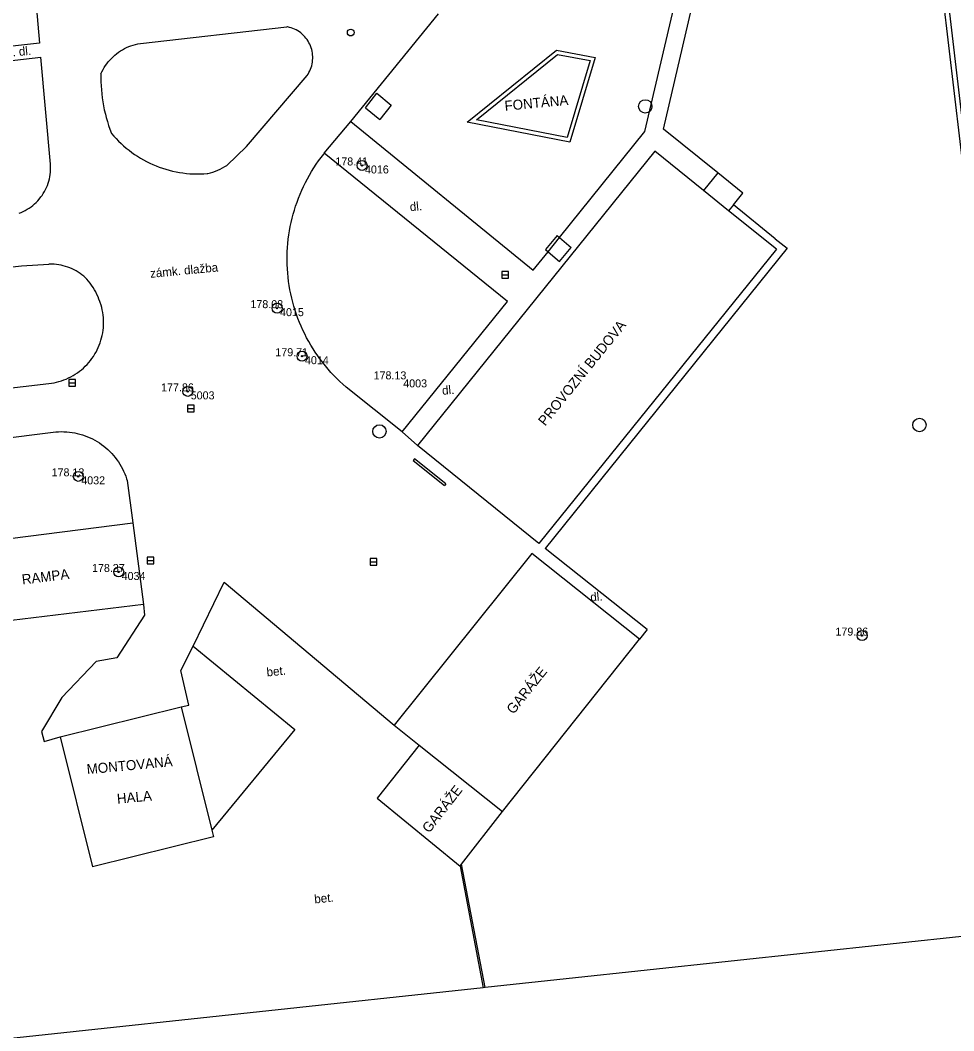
# Model space of a CAD drawing. Extents: x -539515 to -538098, y -1182060 to -1180157.
# Drawn here: x -539294 to -539224, y -1181270.6 to -1181194.9 of the extents above; entities that cross this region are included whole.
import ezdxf

# ---------------------------------------------------------------- set-up
doc = ezdxf.new("R2010")
doc.units = 0
for name, color, linetype in [('Vrstva 1', 7, 'Continuous'), ('Vrstva 13', 7, 'Continuous'), ('Vrstva 21', 7, 'Continuous'), ('Vrstva 22', 7, 'Continuous'), ('Vrstva 23', 7, 'Continuous'), ('Vrstva 27', 7, 'Continuous'), ('Vrstva 28', 7, 'Continuous'), ('Vrstva 40', 7, 'Continuous'), ('Vrstva 41', 7, 'Continuous'), ('Vrstva 68', 7, 'Continuous'), ('Vrstva 88', 7, 'Continuous')]:
    doc.layers.add(name, color=color, linetype=linetype)

msp = doc.modelspace()

# ---------------------------------------------------------------- linework, layer by layer
at = {"layer": 'Vrstva 1'}
for p, q in [((-539246.42, -1181204.7), (-539264.22, -1181226.76)), ((-539237.29, -1181212.03), (-539255.115, -1181234.107)), ((-539255.115, -1181234.107), (-539264.22, -1181226.76)), ((-539285.57, -1181232.55), (-539284.79, -1181238.68)), ((-539255.644, -1181234.863), (-539265.99, -1181247.73)), ((-539247.571, -1181241.284), (-539255.644, -1181234.863)), ((-539257.852, -1181254.21), (-539247.571, -1181241.284)), ((-539291.02, -1181248.59), (-539281.95, -1181246.35)), ((-539291.02, -1181248.59), (-539288.61, -1181258.34)), ((-539279.54, -1181256.1), (-539288.61, -1181258.34))]:
    msp.add_line(p, q, dxfattribs=at)
for points in [[(-539242.774, -1181207.642), (-539246.42, -1181204.7)], [(-539240.891, -1181209.161), (-539242.774, -1181207.642)], [(-539237.29, -1181212.03), (-539240.891, -1181209.161)], [(-539284.79, -1181238.68), (-539297.997, -1181240.285), (-539298.761, -1181234.225), (-539285.57, -1181232.55)], [(-539281.95, -1181246.35), (-539279.661, -1181255.611), (-539279.54, -1181256.1)], [(-539265.99, -1181247.73), (-539264.107, -1181249.236), (-539257.852, -1181254.21)], [(-539264.107, -1181249.236), (-539267.251, -1181253.192), (-539261.04, -1181258.3), (-539260.918, -1181258.143), (-539257.852, -1181254.21)]]:
    msp.add_lwpolyline(points, dxfattribs=at)
at = {"layer": 'Vrstva 13'}
for p, q in [((-539247.18, -1181203.22), (-539243.07, -1181185.65)), ((-539245.78, -1181203.04), (-539241.83, -1181186.08)), ((-539292.58, -1181196.58), (-539296.413, -1181197.009)), ((-539260.498, -1181202.509), (-539253.799, -1181197.109)), ((-539253.799, -1181197.109), (-539250.902, -1181197.657)), ((-539296.519, -1181198.119), (-539292.47, -1181197.64)), ((-539259.81, -1181202.339), (-539253.719, -1181197.429)), ((-539253.719, -1181197.429), (-539251.283, -1181197.889)), ((-539251.283, -1181197.889), (-539253, -1181203.674)), ((-539250.902, -1181197.657), (-539252.791, -1181204.02)), ((-539268.14, -1181201.43), (-539267.28, -1181200.35)), ((-539267.28, -1181200.35), (-539266.2, -1181201.24)), ((-539268.14, -1181201.43), (-539267.06, -1181202.32)), ((-539266.2, -1181201.24), (-539267.06, -1181202.32)), ((-539269.22, -1181202.46), (-539255.54, -1181213.6)), ((-539253, -1181203.674), (-539259.81, -1181202.339)), ((-539252.791, -1181204.02), (-539260.498, -1181202.509)), ((-539253.58, -1181211.166), (-539247.18, -1181203.22)), ((-539257.48, -1181215.97), (-539271.22, -1181204.85)), ((-539241.711, -1181206.324), (-539242.774, -1181207.642)), ((-539240.53, -1181208.72), (-539239.82, -1181207.85)), ((-539240.53, -1181208.72), (-539240.891, -1181209.161)), ((-539237.39, -1181211.25), (-539240.53, -1181208.72)), ((-539237.39, -1181211.25), (-539236.503, -1181211.965)), ((-539236.503, -1181211.965), (-539254.661, -1181234.469)), ((-539254.435, -1181212.227), (-539253.58, -1181212.96)), ((-539253.58, -1181212.96), (-539252.7, -1181211.92)), ((-539265.37, -1181225.74), (-539257.48, -1181215.97)), ((-539264.46, -1181227.765), (-539264.56, -1181227.89)), ((-539264.56, -1181227.89), (-539262.199, -1181229.767)), ((-539262.099, -1181229.642), (-539264.46, -1181227.765)), ((-539262.099, -1181229.642), (-539262.199, -1181229.767)), ((-539246.998, -1181240.564), (-539254.661, -1181234.469)), ((-539246.998, -1181240.564), (-539247.571, -1181241.284)), ((-539281.06, -1181241.8), (-539273.42, -1181248.06)), ((-539273.42, -1181248.06), (-539279.661, -1181255.611))]:
    msp.add_line(p, q, dxfattribs=at)
for points in [[(-539241.711, -1181206.324), (-539245.78, -1181203.04)], [(-539239.82, -1181207.85), (-539241.711, -1181206.324)], [(-539255.54, -1181213.6), (-539254.435, -1181212.227), (-539253.58, -1181211.166)], [(-539253.75, -1181211.02), (-539254.63, -1181212.06), (-539254.435, -1181212.227)], [(-539253.75, -1181211.02), (-539253.58, -1181211.166), (-539252.7, -1181211.92)]]:
    msp.add_lwpolyline(points, dxfattribs=at)
at = {"layer": 'Vrstva 21'}
for centre, radius in [((-539268.39, -1181205.76), 0.375), ((-539268.39, -1181205.76), 0.05), ((-539274.76, -1181216.46), 0.375), ((-539274.76, -1181216.46), 0.05), ((-539272.89, -1181220.06), 0.375), ((-539272.89, -1181220.06), 0.05), ((-539281.46, -1181222.7), 0.375), ((-539281.46, -1181222.7), 0.05), ((-539289.67, -1181229.07), 0.375), ((-539289.67, -1181229.07), 0.05), ((-539286.64, -1181236.24), 0.375), ((-539286.64, -1181236.24), 0.05), ((-539230.88, -1181241.01), 0.375), ((-539230.88, -1181241.01), 0.05)]:
    msp.add_circle(centre, radius, dxfattribs=at)
at = {"layer": 'Vrstva 27'}
for p, q in [((-539257.9, -1181213.96), (-539257.4, -1181213.96)), ((-539290.39, -1181222.05), (-539289.89, -1181222.05)), ((-539281.47, -1181223.99), (-539280.97, -1181223.99)), ((-539284.5, -1181235.37), (-539284, -1181235.37)), ((-539267.78, -1181235.47), (-539267.28, -1181235.47))]:
    msp.add_line(p, q, dxfattribs=at)
for points in [[(-539257.9, -1181214.21), (-539257.4, -1181214.21), (-539257.4, -1181213.71), (-539257.9, -1181213.71)], [(-539290.39, -1181222.3), (-539289.89, -1181222.3), (-539289.89, -1181221.8), (-539290.39, -1181221.8)], [(-539281.47, -1181224.24), (-539280.97, -1181224.24), (-539280.97, -1181223.74), (-539281.47, -1181223.74)], [(-539284.5, -1181235.62), (-539284, -1181235.62), (-539284, -1181235.12), (-539284.5, -1181235.12)], [(-539267.78, -1181235.72), (-539267.28, -1181235.72), (-539267.28, -1181235.22), (-539267.78, -1181235.22)]]:
    msp.add_lwpolyline(points, close=True, dxfattribs=at)
for centre in [(-539247.14, -1181201.33), (-539267.08, -1181225.7), (-539226.58, -1181225.22)]:
    msp.add_circle(centre, 0.5, dxfattribs=at)
at = {"layer": 'Vrstva 28'}
msp.add_circle((-539269.24, -1181195.8), 0.25, dxfattribs=at)
at = {"layer": 'Vrstva 68'}
msp.add_line((-539226.807, -1181176.359), (-539216.629, -1181262.839), dxfattribs=at)
for points in [[(-539218.64, -1181242.5), (-539228.76, -1181156.37)], [(-539216.292, -1181262.8), (-539216.629, -1181262.839), (-539259.16, -1181267.405), (-539259.309, -1181267.421), (-539292.857, -1181271.023), (-539319.19, -1181273.85)]]:
    msp.add_lwpolyline(points, dxfattribs=at)
at = {"layer": 'Vrstva 88'}
for p, q in [((-539293.25, -1181189), (-539292.58, -1181196.58)), ((-539269.22, -1181202.46), (-539262.66, -1181194.38)), ((-539285, -1181196.61), (-539274.04, -1181195.36)), ((-539291.76, -1181205.66), (-539292.47, -1181197.64)), ((-539277.05, -1181204.33), (-539272.51, -1181199.02)), ((-539271.22, -1181204.85), (-539269.22, -1181202.46)), ((-539278.52, -1181205.76), (-539277.05, -1181204.33)), ((-539314.8, -1181215.68), (-539293.93, -1181213.28)), ((-539293.93, -1181213.28), (-539291.89, -1181213.17)), ((-539313.77, -1181224.67), (-539291.87, -1181222.11)), ((-539265.37, -1181225.74), (-539269.58, -1181222.38)), ((-539297.51, -1181226.52), (-539291.55, -1181225.76)), ((-539265.37, -1181225.74), (-539264.22, -1181226.76)), ((-539286.01, -1181229.38), (-539285.57, -1181232.55)), ((-539281.06, -1181241.8), (-539278.72, -1181237)), ((-539278.72, -1181237), (-539265.99, -1181247.73)), ((-539284.79, -1181238.68), (-539284.71, -1181239.48)), ((-539284.71, -1181239.48), (-539286.79, -1181242.67)), ((-539281.98, -1181243.63), (-539281.06, -1181241.8)), ((-539288.33, -1181242.95), (-539290.9, -1181245.65)), ((-539286.79, -1181242.67), (-539288.33, -1181242.95)), ((-539281.38, -1181246.22), (-539281.98, -1181243.63)), ((-539290.9, -1181245.65), (-539292.43, -1181248.2)), ((-539281.95, -1181246.35), (-539281.38, -1181246.22)), ((-539292.43, -1181248.2), (-539292.24, -1181248.94)), ((-539292.24, -1181248.94), (-539291.02, -1181248.59)), ((-539261.04, -1181258.3), (-539259.309, -1181267.421)), ((-539259.16, -1181267.405), (-539260.918, -1181258.143))]:
    msp.add_line(p, q, dxfattribs=at)
for points in [[(-539272.51, -1181199.02), (-539272.435, -1181198.906), (-539272.366, -1181198.787), (-539272.304, -1181198.665), (-539272.25, -1181198.54), (-539272.203, -1181198.411), (-539272.163, -1181198.28), (-539272.132, -1181198.147), (-539272.108, -1181198.012), (-539272.092, -1181197.876), (-539272.084, -1181197.739), (-539272.084, -1181197.602), (-539272.092, -1181197.466), (-539272.108, -1181197.33), (-539272.132, -1181197.195), (-539272.164, -1181197.062), (-539272.2, -1181196.94), (-539272.25, -1181196.802), (-539272.305, -1181196.676), (-539272.366, -1181196.554), (-539272.435, -1181196.436), (-539272.511, -1181196.322), (-539272.593, -1181196.212), (-539272.681, -1181196.107), (-539272.775, -1181196.008), (-539272.875, -1181195.915), (-539272.981, -1181195.827), (-539273.091, -1181195.746), (-539273.205, -1181195.671), (-539273.324, -1181195.603), (-539273.447, -1181195.542), (-539273.573, -1181195.489), (-539273.702, -1181195.443), (-539273.833, -1181195.404), (-539273.967, -1181195.373), (-539274.04, -1181195.36)], [(-539287.97, -1181198.89), (-539287.896, -1181198.73), (-539287.815, -1181198.574), (-539287.727, -1181198.422), (-539287.632, -1181198.274), (-539287.531, -1181198.13), (-539287.423, -1181197.992), (-539287.309, -1181197.858), (-539287.189, -1181197.729), (-539287.063, -1181197.607), (-539286.99, -1181197.54), (-539286.932, -1181197.49), (-539286.796, -1181197.379), (-539286.654, -1181197.274), (-539286.508, -1181197.176), (-539286.358, -1181197.085), (-539286.204, -1181197), (-539286.046, -1181196.923), (-539285.885, -1181196.853), (-539285.72, -1181196.79), (-539285.553, -1181196.735), (-539285.384, -1181196.688), (-539285.213, -1181196.648), (-539285, -1181196.61)], [(-539287.97, -1181198.89), (-539287.974, -1181199.192), (-539287.97, -1181199.493), (-539287.957, -1181199.795), (-539287.937, -1181200.096), (-539287.909, -1181200.397), (-539287.873, -1181200.696), (-539287.829, -1181200.995), (-539287.777, -1181201.292), (-539287.717, -1181201.588), (-539287.64, -1181201.92), (-539287.574, -1181202.174), (-539287.491, -1181202.464), (-539287.4, -1181202.752), (-539287.302, -1181203.037), (-539287.18, -1181203.36)], [(-539287.18, -1181203.36), (-539287.009, -1181203.557), (-539286.833, -1181203.749), (-539286.65, -1181203.936), (-539286.462, -1181204.116), (-539286.269, -1181204.291), (-539286.07, -1181204.46), (-539285.866, -1181204.623), (-539285.657, -1181204.779), (-539285.444, -1181204.929), (-539285.226, -1181205.072), (-539285.004, -1181205.209), (-539284.777, -1181205.339), (-539284.547, -1181205.461), (-539284.313, -1181205.577), (-539284.076, -1181205.685), (-539283.836, -1181205.786), (-539283.592, -1181205.88), (-539283.346, -1181205.966), (-539283.097, -1181206.044), (-539282.846, -1181206.115), (-539282.593, -1181206.178), (-539282.338, -1181206.233), (-539282.082, -1181206.281), (-539281.824, -1181206.32), (-539281.565, -1181206.352), (-539281.305, -1181206.376), (-539281.045, -1181206.391), (-539280.784, -1181206.399), (-539280.523, -1181206.399), (-539280.263, -1181206.391), (-539280.002, -1181206.374), (-539279.95, -1181206.37)], [(-539273.962, -1181213.824), (-539273.985, -1181213.507), (-539273.999, -1181213.189), (-539274.006, -1181212.871), (-539274.004, -1181212.553), (-539273.995, -1181212.235), (-539273.978, -1181211.918), (-539273.952, -1181211.601), (-539273.919, -1181211.284), (-539273.878, -1181210.969), (-539273.828, -1181210.655), (-539273.771, -1181210.342), (-539273.706, -1181210.03), (-539273.633, -1181209.721), (-539273.553, -1181209.413), (-539273.465, -1181209.107), (-539273.369, -1181208.804), (-539273.265, -1181208.503), (-539273.154, -1181208.205), (-539273.036, -1181207.91), (-539272.91, -1181207.618), (-539272.777, -1181207.329), (-539272.636, -1181207.044), (-539272.489, -1181206.762), (-539272.334, -1181206.484), (-539272.172, -1181206.21), (-539272.004, -1181205.94), (-539271.829, -1181205.675), (-539271.647, -1181205.414), (-539271.459, -1181205.157), (-539271.264, -1181204.906), (-539271.22, -1181204.85)], [(-539294.107, -1181209.337), (-539293.949, -1181209.275), (-539293.795, -1181209.205), (-539293.643, -1181209.129), (-539293.496, -1181209.045), (-539293.352, -1181208.954), (-539293.213, -1181208.856), (-539293.079, -1181208.753), (-539292.95, -1181208.642), (-539292.826, -1181208.526), (-539292.708, -1181208.405), (-539292.595, -1181208.277), (-539292.47, -1181208.12), (-539292.389, -1181208.008), (-539292.296, -1181207.866), (-539292.209, -1181207.72), (-539292.13, -1181207.57), (-539292.057, -1181207.417), (-539291.992, -1181207.26), (-539291.934, -1181207.1), (-539291.884, -1181206.938), (-539291.842, -1181206.774), (-539291.807, -1181206.607), (-539291.78, -1181206.44), (-539291.762, -1181206.271), (-539291.751, -1181206.102), (-539291.748, -1181205.932), (-539291.753, -1181205.762), (-539291.76, -1181205.66)], [(-539279.95, -1181206.37), (-539279.759, -1181206.318), (-539279.57, -1181206.259), (-539279.383, -1181206.192), (-539279.2, -1181206.117), (-539279.019, -1181206.035), (-539278.842, -1181205.946), (-539278.669, -1181205.85), (-539278.52, -1181205.76)], [(-539289.13, -1181214.18), (-539289.26, -1181214.064), (-539289.396, -1181213.955), (-539289.536, -1181213.852), (-539289.681, -1181213.755), (-539289.83, -1181213.665), (-539289.983, -1181213.582), (-539290.14, -1181213.507), (-539290.3, -1181213.438), (-539290.463, -1181213.377), (-539290.629, -1181213.324), (-539290.797, -1181213.278), (-539290.967, -1181213.24), (-539291.139, -1181213.209), (-539291.311, -1181213.187), (-539291.485, -1181213.173), (-539291.659, -1181213.166), (-539291.833, -1181213.168), (-539291.89, -1181213.17)], [(-539269.58, -1181222.38), (-539269.819, -1181222.17), (-539270.053, -1181221.954), (-539270.281, -1181221.733), (-539270.504, -1181221.506), (-539270.72, -1181221.273), (-539270.931, -1181221.035), (-539271.136, -1181220.792), (-539271.335, -1181220.543), (-539271.527, -1181220.29), (-539271.713, -1181220.032), (-539271.893, -1181219.769), (-539272.065, -1181219.502), (-539272.231, -1181219.231), (-539272.39, -1181218.955), (-539272.542, -1181218.676), (-539272.687, -1181218.393), (-539272.825, -1181218.106), (-539272.956, -1181217.816), (-539273.079, -1181217.523), (-539273.195, -1181217.227), (-539273.303, -1181216.927), (-539273.404, -1181216.626), (-539273.497, -1181216.322), (-539273.583, -1181216.015), (-539273.66, -1181215.707), (-539273.73, -1181215.397), (-539273.793, -1181215.085), (-539273.847, -1181214.771), (-539273.893, -1181214.457), (-539273.932, -1181214.141), (-539273.962, -1181213.824)], [(-539288.05, -1181215.97), (-539288.117, -1181215.785), (-539288.191, -1181215.603), (-539288.272, -1181215.424), (-539288.361, -1181215.248), (-539288.456, -1181215.076), (-539288.559, -1181214.908), (-539288.668, -1181214.745), (-539288.784, -1181214.586), (-539288.907, -1181214.432), (-539289.035, -1181214.283), (-539289.13, -1181214.18)], [(-539291.87, -1181222.11), (-539291.68, -1181222.085), (-539291.491, -1181222.052), (-539291.303, -1181222.012), (-539291.118, -1181221.963), (-539290.935, -1181221.907), (-539290.754, -1181221.843), (-539290.576, -1181221.772), (-539290.401, -1181221.694), (-539290.229, -1181221.608), (-539290.061, -1181221.515), (-539289.898, -1181221.415), (-539289.738, -1181221.308), (-539289.583, -1181221.195), (-539289.433, -1181221.076), (-539289.288, -1181220.95), (-539289.149, -1181220.819), (-539289.015, -1181220.682), (-539288.887, -1181220.539), (-539288.765, -1181220.391), (-539288.649, -1181220.238), (-539288.54, -1181220.08), (-539288.42, -1181219.89), (-539288.341, -1181219.752), (-539288.252, -1181219.582), (-539288.171, -1181219.409), (-539288.097, -1181219.232), (-539288.03, -1181219.052), (-539287.97, -1181218.87), (-539287.919, -1181218.685), (-539287.875, -1181218.498), (-539287.839, -1181218.31), (-539287.811, -1181218.12), (-539287.79, -1181217.93), (-539287.778, -1181217.738), (-539287.774, -1181217.546), (-539287.778, -1181217.355), (-539287.789, -1181217.163), (-539287.809, -1181216.973), (-539287.837, -1181216.783), (-539287.872, -1181216.594), (-539287.915, -1181216.407), (-539287.966, -1181216.223), (-539288.025, -1181216.04), (-539288.05, -1181215.97)], [(-539291.55, -1181225.76), (-539291.349, -1181225.738), (-539291.148, -1181225.725), (-539290.946, -1181225.719), (-539290.744, -1181225.721), (-539290.542, -1181225.732), (-539290.341, -1181225.75), (-539290.141, -1181225.776), (-539289.941, -1181225.81), (-539289.744, -1181225.852), (-539289.548, -1181225.902), (-539289.354, -1181225.96), (-539289.163, -1181226.025), (-539288.975, -1181226.098), (-539288.789, -1181226.178), (-539288.607, -1181226.265), (-539288.429, -1181226.359), (-539288.254, -1181226.461), (-539288.084, -1181226.569), (-539287.917, -1181226.684), (-539287.756, -1181226.806), (-539287.6, -1181226.933), (-539287.448, -1181227.067), (-539287.302, -1181227.207), (-539287.162, -1181227.352), (-539287.028, -1181227.503), (-539286.9, -1181227.659), (-539286.778, -1181227.82), (-539286.662, -1181227.986), (-539286.553, -1181228.156), (-539286.451, -1181228.331), (-539286.356, -1181228.509), (-539286.268, -1181228.691), (-539286.188, -1181228.876), (-539286.114, -1181229.064), (-539286.049, -1181229.255), (-539286.01, -1181229.38)]]:
    msp.add_lwpolyline(points, dxfattribs=at)

# ---------------------------------------------------------------- texts
at = {"layer": 'Vrstva 22'}
for s, p in [('178.41 ', (-539270.39, -1181205.76)), ('178.08 ', (-539276.76, -1181216.46)), ('179.71 ', (-539274.89, -1181220.06)), ('178.13 ', (-539267.52, -1181221.8)), ('177.86 ', (-539283.46, -1181222.7)), ('178.13 ', (-539291.67, -1181229.07)), ('178.37 ', (-539288.64, -1181236.24)), ('179.86 ', (-539232.88, -1181241.01))]:
    msp.add_text(s, height=0.6, dxfattribs=at).set_placement(p)
at = {"layer": 'Vrstva 23'}
for s, p in [(' 4016', (-539268.39, -1181206.36)), (' 4015', (-539274.76, -1181217.06)), (' 4014', (-539272.89, -1181220.66)), (' 4003', (-539265.52, -1181222.4)), (' 5003', (-539281.46, -1181223.3)), (' 4032', (-539289.67, -1181229.67)), (' 4034', (-539286.64, -1181236.84))]:
    msp.add_text(s, height=0.6, dxfattribs=at).set_placement(p)
at = {"layer": 'Vrstva 40'}
for s, p in [('zám. dl.', (-539296.214, -1181197.746)), ('dl.', (-539264.775, -1181209.196)), ('zámk. dlažba', (-539284.256, -1181214.188)), ('dl.', (-539262.356, -1181222.962)), ('dl.', (-539251.24, -1181238.457)), ('bet.', (-539275.519, -1181244.076)), ('bet.', (-539271.94, -1181261.092))]:
    msp.add_text(s, height=0.65, rotation=5.42156, dxfattribs=at).set_placement(p)
at = {"layer": 'Vrstva 41'}
for s, rotation, p in [('FONTÁNA', 5.42156, (-539257.662, -1181201.667)), ('PROVOZNÍ BUDOVA', 51.10028, (-539254.659, -1181225.34)), ('RAMPA', 6.92898, (-539293.856, -1181237.18)), ('GARÁŽE', 51.50218, (-539257.028, -1181246.954)), ('MONTOVANÁ ', 5.42156, (-539289.003, -1181251.408)), ('GARÁŽE', 52.06494, (-539263.351, -1181255.865)), ('HALA', 5.42156, (-539286.737, -1181253.622))]:
    msp.add_text(s, height=0.75, rotation=rotation, dxfattribs=at).set_placement(p)

doc.saveas('drawing.dxf')
